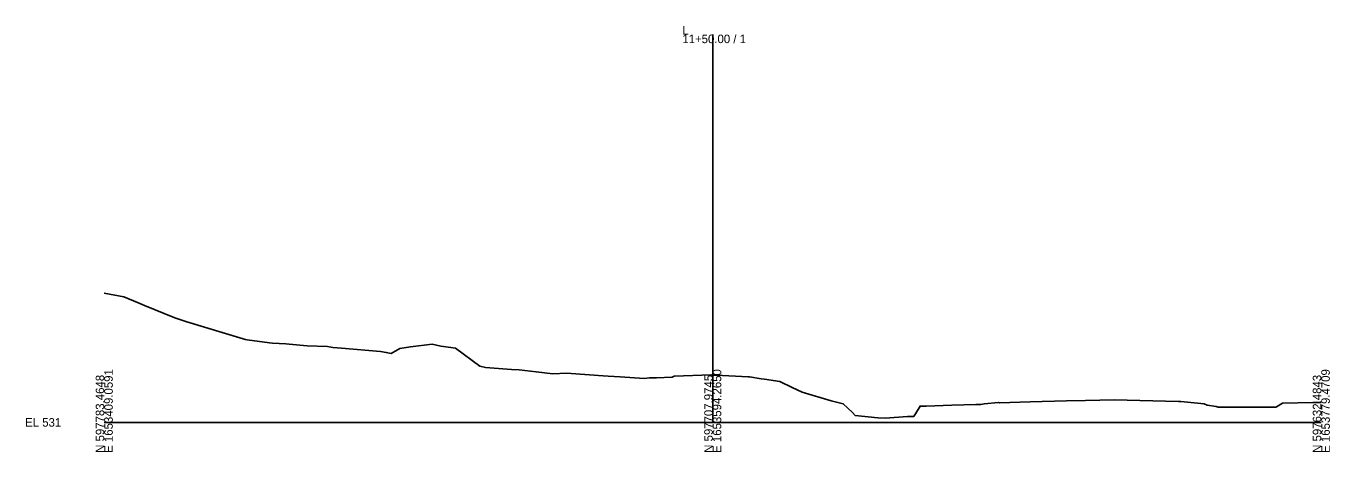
# Model space of a CAD drawing. Extents: x -26 to 403, y -10 to 6021.
# Drawn here: x -25.7 to 402.8, y -9.7 to 130.2 of the extents above; entities that cross this region are included whole.
import ezdxf

# ---------------------------------------------------------------- set-up
doc = ezdxf.new("R2010")
doc.units = 0
for name, color, linetype in [('Default', 7, 'Continuous'), ('Exist Cross Section Cell', 7, 'Continuous'), ('Exist XS Ground Line', 7, 'Continuous')]:
    doc.layers.add(name, color=color, linetype=linetype)

msp = doc.modelspace()

# ---------------------------------------------------------------- linework, layer by layer
at = {"layer": 'Exist Cross Section Cell'}
for p, q in [((200, 0), (200, 127.37)), ((0, 0), (200, 0)), ((200, 0), (400, 0))]:
    msp.add_line(p, q, dxfattribs=at)
at = {"layer": 'Exist XS Ground Line'}
msp.add_lwpolyline([(0, 42.46), (6.41, 41.27), (10.93, 39.34), (13.19, 38.37), (23.17, 34.35), (27.1, 33.07), (45.68, 27.42), (46.31, 27.22), (46.33, 27.21), (46.36, 27.21), (46.99, 27.12), (54.28, 26.14), (55.35, 26.07), (59.66, 25.81), (60.76, 25.68), (66.66, 25.15), (73.35, 24.88), (75.09, 24.64), (78, 24.37), (90.76, 23.29), (92.7, 23.01), (94.27, 22.66), (97.18, 24.22), (100.68, 24.81), (107.75, 25.71), (110.64, 25.02), (111.54, 24.88), (115.43, 24.34), (123.45, 18.51), (125.32, 18), (133.9, 17.32), (136.34, 17.22), (141.96, 16.57), (147.42, 15.96), (151.98, 16.19), (159.46, 15.66), (163.93, 15.32), (165.58, 15.19), (169.6, 15.01), (177.44, 14.44), (179.18, 14.64), (181.52, 14.64), (186.61, 14.91), (187.29, 15.14), (199.51, 15.57), (199.6, 15.57), (200, 15.55), (201.14, 15.5), (211.6, 15.02), (212.07, 14.95), (215.96, 14.34), (217.02, 14.23), (222.01, 13.43), (226.11, 11.42), (229.39, 9.96), (238.93, 7.04), (242.87, 6.1), (245.9, 3.3), (246.77, 2.27), (254.22, 1.45), (256.78, 1.4), (264.02, 1.98), (266.05, 1.91), (267.84, 4.8), (268.16, 5.35), (270.14, 5.37), (278.52, 5.7), (286.47, 5.91), (288.06, 5.91), (289.2, 6.08), (293.9, 6.49), (294.29, 6.44), (304.28, 6.77), (316.29, 7.03), (322.54, 7.21), (331.96, 7.45), (353.09, 6.87), (353.6, 6.86), (353.89, 6.86), (361.55, 6.08), (362.51, 5.71), (365.4, 5.17), (366.07, 5.03), (366.88, 5.03), (373.02, 5.03), (385.13, 5.03), (385.3, 5.16), (387.3, 6.35), (397.24, 6.53), (400, 6.57)], dxfattribs=at)

# ---------------------------------------------------------------- texts
at = {"layer": 'Default'}
msp.add_text('-', height=0.0001, dxfattribs=at).set_placement((0, 0))
at = {"layer": 'Exist Cross Section Cell'}
for s, p in [('L', (190, 127.37)), ('11+50.00 / 1', (190, 124.57)), ('EL 531', (-26, -1.4))]:
    msp.add_text(s, height=2.8, dxfattribs=at).set_placement(p)
for s, p in [('E 1653409.0591', (2.8, -10)), ('E 1653594.2650', (202.8, -10)), ('E 1653779.4709', (402.8, -10)), ('N 597783.4648', (0, -10)), ('N 597707.9745', (200, -10)), ('N 597632.4843', (400, -10))]:
    msp.add_text(s, height=2.8, rotation=90, dxfattribs=at).set_placement(p)

doc.saveas('drawing.dxf')
